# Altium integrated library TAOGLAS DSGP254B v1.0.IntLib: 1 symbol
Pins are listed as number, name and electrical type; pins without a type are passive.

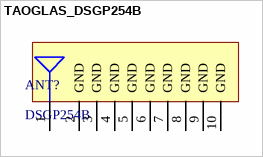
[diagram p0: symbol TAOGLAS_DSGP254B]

## TAOGLAS_DSGP254B
designator ANT?, comment DSGP254B
GPS L1 / GALILEO E1 1575.42MHz 25*25*4mm Ceramic Patch SMD Antenna; ComponentLibStatus: Created; MFG: Taoglas; Temp_High: +85C; Temp_Low: -40C
footprint TAOGLAS_DSGP254B (GPS L1 / GALILEO E1 1575.42MHz 25*25*4mm Ceramic Patch SMD Antenna)
pins: 1 RF FEED, 2 GND, 3 GND, 4 GND, 5 GND, 6 GND, 7 GND, 8 GND, 9 GND, 10 GND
